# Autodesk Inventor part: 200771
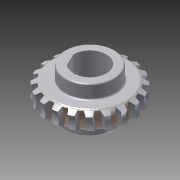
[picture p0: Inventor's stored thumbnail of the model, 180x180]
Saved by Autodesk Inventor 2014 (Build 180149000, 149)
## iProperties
Created: 2007-11
Part Number: 200771
Material: Acetal Resin, White
Document SubType Name: Modeling
Designer: JJ
Density: 1.42 g/cm^3
Mass: 6.62581 g
Surface Area: 30.1995 cm^2
Volume: 4.66606 cm^3
Description: WORM GEAR - 20 TOOTH
Appearance: Smooth - White
CustomPartVersion: 1
Component Category: Lower Component
Author: JJ
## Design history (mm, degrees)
body "Solid1"
node "Tooth Plane"
revolve "Base Body" stored, may be unused: angle "d35" = 90 deg
revolve "Tooth" stored, may be unused: angle "d43" = 90 deg
pattern_circular "Tooth Pattern" dims angle "d46" = 360 deg
workplane "Work Plane15"
workplane "Work Plane16"
sketch "Sketch11"
  geometry: L1 (3.836, -4.614)-(5.999, -0.106) reference; L2 (6.099, -0.13)-(6.099, -0.13); A1 r 6 centre (0, 0) between (5.999, -0.106) and (3.836, -4.614) reference; A2 r 6.1 centre (0, 0) between (6.099, -0.13) and (6.099, -0.13)
  constraints: 2 end point, 2 point on circle, 1 centre point, 1 other
  dimensions: "d101" = 0.1 radial gap between concentric circles of A1 A2
extrude "Extrusion1" cut sketch "Sketch11" stored distance "d99" = 10; taper "d100" = 0 deg
sketch "Sketch12"
  geometry: L1 (5.999, -0.106)-(3.836, -4.614) reference; C1 r 9 at (0, 0); A1 r 12.952 centre (0, 0) between (-5.209, -11.858) and (-2.755, -12.655) reference; 3 further points
  constraints: 1 centre point, 1 coincident, 1 other
  dimensions: "d103" = 18 diameter of C1
extrude "Extrusion2" join sketch "Sketch12" distance "d104" = 5; taper "d105" = 0 deg
mirror "Mirror1"
fillet "Fillet1" dims "d106" = 0.5
sketch "Base Body Sketch"
  geometry: L1 (0, -10.144)-(0, 10.144) reference; L2 (0, 3.25)-(12.952, 3.25); L3 (0, 3.25)-(0, -3.25); L4 (0, -3.25)-(12.952, -3.25); L5 (12.952, 3.25)-(15.301, 2.167); L6 (12.952, -3.25)-(15.301, -2.167); L7 (-4.924, 0)-(24.154, 0) reference; A1 r 5.174 centre (20, 0) between (15.301, 2.167) and (15.301, -2.167); A2 r 7.246 centre (6.476, 0) between (0, 3.25) and (12.952, 3.25)
  constraints: 10 end point, 6 point on circle, 3 perpendicular, 3 point on line, 2 centre point, 1 collinear
  dimensions: "d30" = 49.5082 deg angle of L6 L5 (= 2 x da_fi); "d31" = 5.17445 radius of A1 (= da_aw - 0.5 x da_da); "d32" = 6.5 distance of L2.start L3.end (= da_b); "d33" = 20 distance from line of L1 A1.centre (= da_aw); "d50" = 24.7541 deg angle of L5 L2 (= da_fi)
sketch "Tooth Sketch"
  geometry: L1 (10, 2.498)-(10, -2.498) reference; L2 (-11.604, 0)-(-0.376, 0) reference; L3 (-10, 1.614)-(-10, -1.614); L4 (-10, -1.614)-(-5.084, -1.614); L5 (-5.084, -1.614)-(-2.916, -0.825); L6 (-2.916, -0.825)-(-2.916, 0); L7 (-2.916, 0.825)-(-5.084, 1.614); L8 (-5.084, 1.614)-(-10, 1.614); L9 (-2.916, 0.825)-(-2.916, 0); L10 (-4, 0)-(-4, -1.219)
  constraints: 16 end point, 4 perpendicular, 3 equal length, 2 point on line, 1 midpoint, 1 parallel, 1 vertical
  dimensions: "d38" = 20 distance between parallel lines of L1 L3 (= da_aw); "d39" = 20 deg angle of L7 L8 (= da_alfat); "d40" = 4.91572 distance of L7.end L3.start (= 0.5 x da_df1); "d41" = 6 distance between parallel lines of L3 L10; "d42" = 1.2192 distance of L10.start L10.end (= 0.3 x da_px)
sketch "Sketch10"
  geometry: C1 r 12.952 at (0, 0) reference; C2 r 13.5 at (0, 0)
  constraints: 1 centre point, 1 coincident
  dimensions: "d81" = 27 diameter of C2
body "Srf1"
node "Reference1"
node "Reference2"
extrude_surface "ExtrusionSrf1" dims "d82" = 6.5 (= da_b), "d83" = 0
other parameters: "da_aw" = 20 [user parameter; used in 5 equation terms], "da_fi" = 24.7541 deg [user parameter; used in 2 equation terms], "da_b" = 6.5 [user parameter; used in 2 equation terms], "da_df" = 23.95922 [user parameter], "da_da" = 29.65111 [user parameter; used in 1 equation term], "da_beta" = 0.99669 [user parameter; used in 1 equation term], "da_alfat" = 20 deg [user parameter; used in 1 equation term], "da_df1" = 9.83145 [user parameter; used in 1 equation term], "da_da1" = 15.52334 [user parameter], "da_d1" = 12.93611 [user parameter], "da_px" = 4.064 [user parameter; used in 1 equation term], "d2" = 36.792 (derived), "d4" = 60 deg (derived), "d6" = 30 deg (derived), "d10" = 14 (derived), "d15" = 0, "d17" = 20 deg (derived), "d19" = 9 (derived), "d21" = 13.635 (derived), "d23" = 2.35 (derived), "d25" = 11.5 (derived), "d27" = 0 (derived), "d36" = 7 deg, "d37" = -0.99669 (computed from da_rightdir, da_beta), "d74" = 0, "da_dw" = 25.87223 [user parameter], "da_rightdir" = 0 [user parameter; used in 1 equation term], "d87" = 0, "d88" = 0, "d89" = 0, "d91" = 9 deg (computed from da_z), "d94" = 180 deg, "d96" = 0, "d97" = 0
